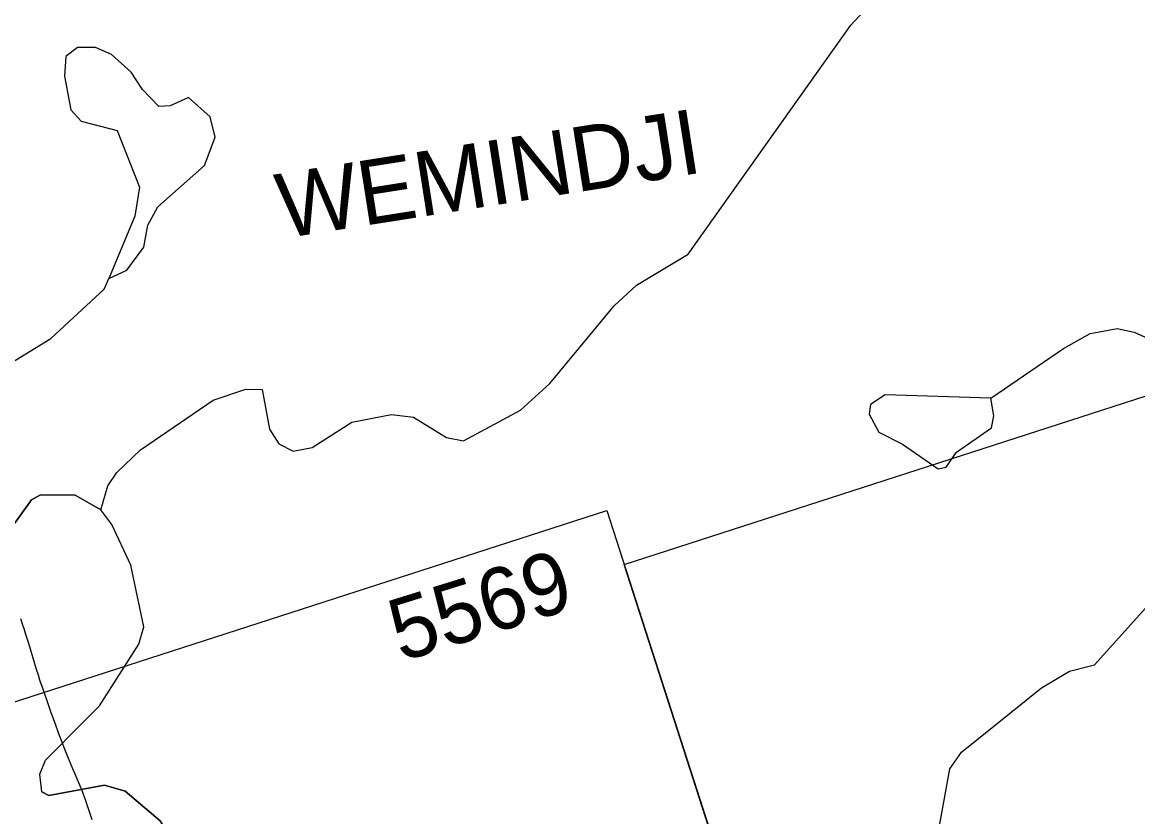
# Model space of a CAD drawing. Extents: x 643342 to 646936, y 5873857 to 5876103.
# Drawn here: x 646462.2 to 646548.6, y 5875362.4 to 5875423.9 of the extents above; entities that cross this region are included whole.
import ezdxf

# ---------------------------------------------------------------- set-up
doc = ezdxf.new("R2010")
doc.units = 0
doc.layers.add('Niveau 63', color=7, linetype='Continuous')
doc.layers.add('Par défaut', color=7, linetype='Continuous')

msp = doc.modelspace()

# ---------------------------------------------------------------- linework, layer by layer
at = {"layer": 'Niveau 63'}
for p, q in [((646465.553, 5875421.253), (646465.451, 5875419.718)), ((646465.451, 5875419.718), (646465.94, 5875417.123)), ((646473.627, 5875417.421), (646472.742, 5875417.383)), ((646475.043, 5875418.069), (646473.627, 5875417.421)), ((646476.713, 5875416.591), (646475.043, 5875418.069)), ((646465.94, 5875417.123), (646466.724, 5875416.254)), ((646466.724, 5875416.254), (646469.532, 5875415.522)), ((646469.532, 5875415.522), (646471.255, 5875411.136)), ((646472.668, 5875409.617), (646476.275, 5875412.817)), ((646471.255, 5875411.136), (646470.899, 5875408.894)), ((646470.259, 5875404.724), (646471.581, 5875406.49)), ((646528.996, 5875395.055), (646527.855, 5875394.329)), ((646537.174, 5875394.803), (646528.996, 5875395.055)), ((646537.428, 5875393.446), (646537.174, 5875394.803)), ((646527.855, 5875394.329), (646527.753, 5875393.563)), ((646527.753, 5875393.563), (646528.519, 5875392.166)), ((646537.229, 5875392.524), (646537.428, 5875393.446)), ((646528.519, 5875392.166), (646530.345, 5875391.238)), ((646530.345, 5875391.238), (646533.113, 5875389.345)), ((646533.113, 5875389.345), (646533.723, 5875389.461))]:
    msp.add_line(p, q, dxfattribs=at)
for points in [[(646468.259, 5875386.167), (646468.796, 5875388.033), (646469.486, 5875389.053), (646471.336, 5875390.802), (646476.968, 5875394.644), (646479.484, 5875395.505), (646480.743, 5875395.481), (646481.327, 5875392.414), (646482.033, 5875391.27), (646483.153, 5875390.717), (646484.629, 5875390.99), (646487.701, 5875392.951), (646490.768, 5875393.535), (646492.459, 5875393.335), (646495.033, 5875391.776), (646496.349, 5875391.518), (646500.757, 5875393.872), (646503.041, 5875395.952), (646508.008, 5875401.957), (646509.742, 5875403.546), (646513.756, 5875405.959), (646526.356, 5875423.672), (646528.462, 5875425.988)], [(646470.899, 5875408.894), (646468.863, 5875404.079), (646470.259, 5875404.724), (646471.581, 5875406.49), (646471.899, 5875408.201), (646472.668, 5875409.617), (646476.275, 5875412.817), (646477.123, 5875415.015), (646476.713, 5875416.591), (646475.043, 5875418.069), (646473.627, 5875417.421), (646472.742, 5875417.383), (646471.485, 5875418.684), (646470.603, 5875420.043), (646469.073, 5875421.402), (646467.835, 5875421.936), (646466.437, 5875421.939), (646465.553, 5875421.253), (646465.451, 5875419.718), (646465.94, 5875417.123), (646466.724, 5875416.254), (646469.532, 5875415.522), (646471.255, 5875411.136), (646470.899, 5875408.894)], [(646467.835, 5875421.936), (646466.437, 5875421.939), (646465.553, 5875421.253)], [(646470.603, 5875420.043), (646469.073, 5875421.402), (646467.835, 5875421.936)], [(646472.742, 5875417.383), (646471.485, 5875418.684), (646470.603, 5875420.043)], [(646476.275, 5875412.817), (646477.123, 5875415.015), (646476.713, 5875416.591)], [(646471.581, 5875406.49), (646471.899, 5875408.201), (646472.668, 5875409.617)], [(646470.899, 5875408.894), (646468.863, 5875404.079), (646470.259, 5875404.724)], [(646459.194, 5875395.917), (646460.847, 5875397.25), (646464.391, 5875399.427), (646468.507, 5875403.253), (646468.863, 5875404.079)], [(646537.174, 5875394.803), (646542.826, 5875398.648), (646544.891, 5875399.803), (646546.976, 5875400.192), (646548.295, 5875399.913), (646553.852, 5875397.407), (646556.213, 5875397.717), (646557.608, 5875397.086), (646558.137, 5875394.882), (646557.682, 5875393.271), (646556.657, 5875391.936), (646555.885, 5875389.891), (646556.663, 5875385.721)], [(646537.174, 5875394.803), (646542.826, 5875398.648), (646544.891, 5875399.803), (646546.976, 5875400.192), (646548.295, 5875399.913), (646553.852, 5875397.407), (646556.213, 5875397.717), (646557.608, 5875397.086), (646558.137, 5875394.882), (646557.682, 5875393.271), (646556.657, 5875391.936), (646555.885, 5875389.891), (646556.663, 5875385.721)], [(646519.225, 5875349.576), (646508.785, 5875381.933), (646560.176, 5875398.515), (646570.617, 5875366.157), (646519.225, 5875349.576)], [(646537.174, 5875394.803), (646528.996, 5875395.055), (646527.855, 5875394.329), (646527.753, 5875393.563), (646528.519, 5875392.166), (646530.345, 5875391.238), (646533.113, 5875389.345), (646533.723, 5875389.461), (646534.532, 5875390.621), (646537.229, 5875392.524), (646537.428, 5875393.446), (646537.174, 5875394.803)], [(646537.428, 5875393.446), (646537.174, 5875394.803), (646528.996, 5875395.055), (646527.855, 5875394.329), (646527.753, 5875393.563), (646528.519, 5875392.166), (646530.345, 5875391.238), (646533.113, 5875389.345), (646533.723, 5875389.461), (646534.532, 5875390.621), (646537.229, 5875392.524), (646537.428, 5875393.446)], [(646537.174, 5875394.803), (646528.996, 5875395.055), (646527.855, 5875394.329), (646527.753, 5875393.563), (646528.519, 5875392.166), (646530.345, 5875391.238), (646533.113, 5875389.345), (646533.723, 5875389.461), (646534.532, 5875390.621), (646537.229, 5875392.524), (646537.428, 5875393.446), (646537.174, 5875394.803)], [(646537.428, 5875393.446), (646537.174, 5875394.803), (646528.996, 5875395.055), (646527.855, 5875394.329), (646527.753, 5875393.563), (646528.519, 5875392.166), (646530.345, 5875391.238), (646533.113, 5875389.345), (646533.723, 5875389.461), (646534.532, 5875390.621), (646537.229, 5875392.524), (646537.428, 5875393.446)], [(646533.723, 5875389.461), (646534.532, 5875390.621), (646537.229, 5875392.524)], [(646441.797, 5875367.123), (646442.841, 5875368.34), (646446.01, 5875370.458), (646449.754, 5875373.558), (646452.238, 5875376.56), (646453.559, 5875379.744), (646454.821, 5875381.117), (646457.969, 5875381.957), (646460.469, 5875383.565), (646462.893, 5875386.943), (646463.581, 5875387.334), (646466.257, 5875387.31), (646468.259, 5875386.167)], [(646483.479, 5875350.297), (646482.276, 5875352.537), (646480.884, 5875353.796), (646477.757, 5875354.883), (646476.737, 5875355.573), (646472.854, 5875362.109), (646470.146, 5875364.396), (646468.535, 5875364.851), (646464.227, 5875364.052), (646463.697, 5875364.333), (646463.542, 5875365.705), (646463.976, 5875366.806), (646466.966, 5875369.807), (646468.154, 5875371.007), (646471.209, 5875375.779), (646471.587, 5875377.114), (646470.571, 5875381.895), (646469.104, 5875385.045), (646468.259, 5875386.167), (646466.257, 5875387.31), (646463.581, 5875387.334), (646462.893, 5875386.943), (646460.469, 5875383.565)], [(646483.479, 5875350.297), (646482.276, 5875352.537), (646480.884, 5875353.796), (646477.757, 5875354.883), (646476.737, 5875355.573), (646472.854, 5875362.109), (646470.146, 5875364.396), (646468.535, 5875364.851), (646464.227, 5875364.052), (646463.697, 5875364.333), (646463.542, 5875365.705), (646463.976, 5875366.806), (646466.966, 5875369.807), (646468.154, 5875371.007), (646471.209, 5875375.779), (646471.587, 5875377.114), (646470.571, 5875381.895), (646469.104, 5875385.045), (646468.259, 5875386.167), (646466.257, 5875387.31), (646463.581, 5875387.334), (646462.893, 5875386.943), (646460.469, 5875383.565)], [(646466.966, 5875369.807), (646468.154, 5875371.007), (646471.209, 5875375.779), (646471.587, 5875377.114), (646470.571, 5875381.895), (646469.104, 5875385.045), (646468.259, 5875386.167)], [(646456.043, 5875369.54), (646507.434, 5875386.121), (646517.874, 5875353.763), (646466.483, 5875337.182), (646456.043, 5875369.54)], [(646532.816, 5875359.577), (646534.013, 5875366.123), (646534.903, 5875367.417), (646541.104, 5875372.401), (646543.269, 5875373.694), (646545.217, 5875374.182), (646555.009, 5875385.036), (646556.663, 5875385.721)], [(646467.579, 5875362.167), (646467.192, 5875363.34), (646467.06, 5875363.729), (646466.915, 5875364.139), (646466.798, 5875364.45), (646466.625, 5875364.874), (646466.338, 5875365.531), (646466.081, 5875366.134), (646465.705, 5875367.049), (646465.499, 5875367.566), (646465.448, 5875367.696), (646465.231, 5875368.253), (646465.208, 5875368.313), (646465.015, 5875368.823), (646464.984, 5875368.905), (646464.738, 5875369.57), (646464.464, 5875370.324), (646464.417, 5875370.456), (646464.172, 5875371.145), (646463.803, 5875372.205), (646463.562, 5875372.913), (646463.54, 5875372.98), (646463.415, 5875373.365), (646463.277, 5875373.806), (646462.668, 5875375.819), (646462.45, 5875376.521), (646462.334, 5875376.882), (646462.19, 5875377.315), (646462.048, 5875377.722)], [(646463.697, 5875364.333), (646463.542, 5875365.705), (646463.976, 5875366.806), (646466.966, 5875369.807)], [(646463.697, 5875364.333), (646463.542, 5875365.705), (646463.976, 5875366.806), (646466.966, 5875369.807)], [(646463.697, 5875364.333), (646464.227, 5875364.052), (646468.535, 5875364.851), (646470.146, 5875364.396), (646472.854, 5875362.109), (646476.737, 5875355.573), (646477.757, 5875354.883), (646480.884, 5875353.796), (646482.276, 5875352.537), (646483.479, 5875350.297)], [(646463.697, 5875364.333), (646464.227, 5875364.052), (646468.535, 5875364.851), (646470.146, 5875364.396), (646472.854, 5875362.109), (646476.737, 5875355.573), (646477.757, 5875354.883), (646480.884, 5875353.796), (646482.276, 5875352.537), (646483.479, 5875350.297)]]:
    msp.add_lwpolyline(points, dxfattribs=at)

# ---------------------------------------------------------------- texts
msp.add_text('WEMINDJI', height=5, rotation=8.94112, dxfattribs=at).set_placement((646482.32, 5875407.15))
at = {"layer": 'Par défaut'}
for s, height, rotation, p in [('WEMINDJI', 5, 8.94112, (646482.32, 5875407.15)), ('5569', 4.8, 17.27177, (646491.498, 5875374.382))]:
    msp.add_text(s, height=height, rotation=rotation, dxfattribs=at).set_placement(p)

doc.saveas('drawing.dxf')
